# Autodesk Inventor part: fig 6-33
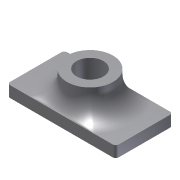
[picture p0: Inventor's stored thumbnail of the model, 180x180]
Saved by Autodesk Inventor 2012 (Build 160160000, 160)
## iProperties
Created: 2004-05
Part Number: fig 6-33
Document SubType Name: Modeling
Designer: CADCIM Technologies
Manufacturer: Standard
Standards Organization: Custom
Density: 1 g/cm^3
Material: Default
Author: CADCIM Technologies
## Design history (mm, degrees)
sketch "Sketch1"
  geometry: L1 (-39.276, -18.692)-(33.721, -18.692); L2 (33.721, -18.692)-(33.721, 19.728); L3 (33.721, 19.728)-(-39.276, 19.728); L4 (-39.276, 19.728)-(-39.276, -18.692)
  constraints: 8 end point, 2 parallel, 1 horizontal, 1 perpendicular
extrude "Extrusion1" new body sketch "Sketch1" distance "d0" = 7.5; taper "d1" = 0 deg
fillet "Fillet1" dims "d2" = 2
sketch "Sketch2"
  geometry: C1 r 15.456 at (-2.778, 0.518)
  constraints: 1 centre point
extrude "Extrusion2" join sketch "Sketch2" distance "d3" = 17.25; taper "d4" = 0 deg
hole "Hole1" diameter "d8" = 18; stored, may be unused: countersink angle "d12" = 90 deg, drill point angle "d14" = 118 deg; dims "d6" = 10, "d7" = 10, "d9" = 6, "d10" = 4, "d11" = 2, "d13" = 8
fillet "Fillet2" dims "d5" = 14
body "Solid1"
